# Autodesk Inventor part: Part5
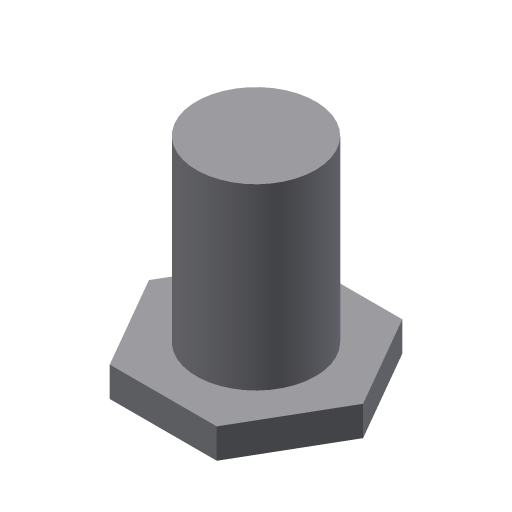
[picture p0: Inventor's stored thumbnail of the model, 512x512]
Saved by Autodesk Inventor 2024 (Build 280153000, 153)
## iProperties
Created: 2008-05
Part Number: Part5
Document SubType Name: Modeling
Designer: CADCIM
Density: 1 g/cm^3
Material: Generic
Appearance: Default
Author: CADCIM
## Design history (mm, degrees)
sketch "Sketch1"
  geometry: C1 r 2 at (-7.12, 11.618)
  constraints: 1 centre point
  dimensions: "d2" = 4 diameter of C1
extrude "Extrusion1" new body sketch "Sketch1" distance "d0" = 6; taper "d1" = 0 deg
sketch "Sketch2"
  geometry: L1 (-3.598, 0)-(-1.799, 3.116); L2 (-1.799, 3.116)-(1.799, 3.116); L3 (1.799, 3.116)-(3.598, 0); L4 (3.598, 0)-(1.799, -3.116); L5 (1.799, -3.116)-(-1.799, -3.116); L6 (-1.799, -3.116)-(-3.598, 0); C1 r 2 at (0, 0) reference; 1 further point
  constraints: 12 end point, 1 coincident, 13 other
extrude "Extrusion2" join sketch "Sketch2" distance "d3" = 1; taper "d4" = 0 deg
body "Solid1"
